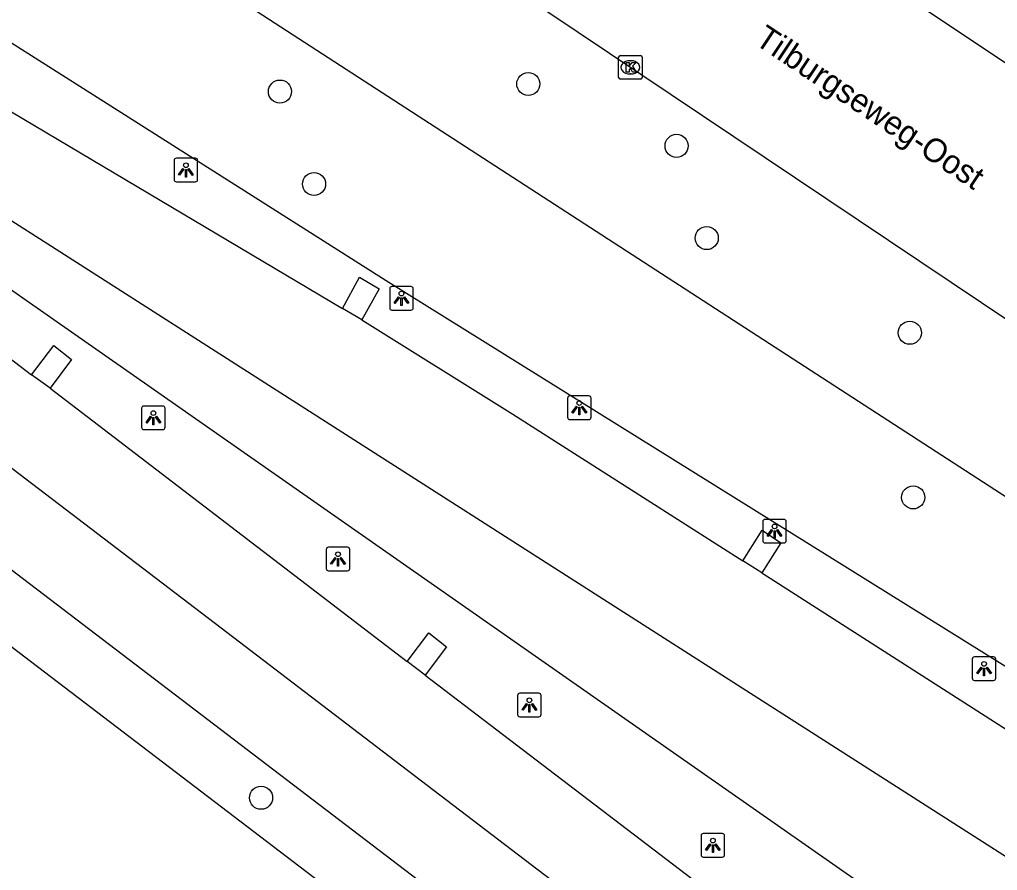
# Model space of a CAD drawing. Extents: x 158352 to 159489, y 383828 to 384597.
# Drawn here: x 158662.39 to 158703.83, y 383993.35 to 384029.38 of the extents above; entities that cross this region are included whole.
import ezdxf

# ---------------------------------------------------------------- set-up
doc = ezdxf.new("R2010")
doc.units = 0
for name, color, linetype in [('IMGEO_Berm_groen', 7, 'Continuous'), ('IMGEO_Boom', 7, 'Continuous'), ('IMGEO_Groenvoorziening', 7, 'Continuous'), ('IMGEO_Kolk', 7, 'Continuous'), ('IMGEO_Lichtpunt', 7, 'Continuous'), ('IMGEO_Openbare_ruimte_label', 7, 'Continuous'), ('IMGEO_Rijbaan_lokaal_open', 7, 'Continuous'), ('IMGEO_Rijbaan_regionaal_gesloten', 7, 'Continuous')]:
    doc.layers.add(name, color=color, linetype=linetype)

msp = doc.modelspace()

# ---------------------------------------------------------------- linework, layer by layer
at = {"layer": 'IMGEO_Berm_groen'}
for points in [[(158809.728, 383931.93), (158795.981, 383941.779), (158765.871, 383961.56), (158707.358, 384000), (158677.929, 384018.316), (158661.741, 384028.584), (158651.483, 384034.675), (158626.962, 384050.112), (158614.378, 384057.858), (158613.62, 384057.184)], [(158658.997, 384020.06), (158719.87, 383977.549)]]:
    msp.add_lwpolyline(points, dxfattribs=at)
at = {"layer": 'IMGEO_Boom'}
for centre in [(158683.946, 384026.656), (158673.421, 384026.335), (158690.228, 384024.035), (158674.866, 384022.42), (158691.508, 384020.131), (158700.113, 384016.119), (158700.256, 384009.149), (158672.622, 383996.426)]:
    msp.add_circle(centre, 0.489, dxfattribs=at)
at = {"layer": 'IMGEO_Groenvoorziening'}
msp.add_lwpolyline([(158631.002, 384057.298), (158666.397, 384033.665), (158718.365, 384000), (158753.016, 383977.553), (158769.011, 383966.352)], dxfattribs=at)
at = {"layer": 'IMGEO_Kolk'}
for p, q in [((158687.848, 384027.86), (158688.7, 384027.86)), ((158687.773, 384026.934), (158687.773, 384027.786)), ((158688.261, 384027.64), (158688.286, 384027.64)), ((158688.774, 384027.786), (158688.774, 384026.934)), ((158688.284, 384027.08), (158688.259, 384027.08)), ((158688.7, 384026.86), (158687.848, 384026.86))]:
    msp.add_line(p, q, dxfattribs=at)
for points in [[(158687.848, 384027.86), (158688.7, 384027.86)], [(158687.773, 384026.934), (158687.773, 384027.786)], [(158688.094, 384027.56), (158688.217, 384027.56), (158688.217, 384027.409), (158688.347, 384027.56), (158688.511, 384027.56), (158688.365, 384027.409), (158688.518, 384027.16), (158688.366, 384027.16), (158688.281, 384027.324), (158688.217, 384027.257), (158688.217, 384027.16), (158688.094, 384027.16), (158688.094, 384027.56)], [(158688.774, 384027.786), (158688.774, 384026.934)], [(158688.7, 384026.86), (158687.848, 384026.86)]]:
    msp.add_lwpolyline(points, dxfattribs=at)
for centre, start, end in [((158687.85, 384027.784), 91.552, 178.448), ((158687.85, 384027.784), 91.552, 178.448), ((158688.698, 384027.784), 1.552, 88.448), ((158688.698, 384027.784), 1.552, 88.448), ((158687.85, 384026.936), 181.552, 268.448), ((158687.85, 384026.936), 181.552, 268.448), ((158688.698, 384026.936), 271.552, 358.448), ((158688.698, 384026.936), 271.552, 358.448)]:
    msp.add_arc(centre, 0.0765, start, end, dxfattribs=at)
for centre, major_axis, ratio, start_param, end_param in [((158688.26, 384027.36), (-0.387, 0.002), 0.722429, 4.712389, 7.853982), ((158688.285, 384027.36), (-0.39, 0.002), 0.717154, 1.570796, 4.712389)]:
    msp.add_ellipse(centre, major_axis=major_axis, ratio=ratio, start_param=start_param, end_param=end_param, dxfattribs=at)
at = {"layer": 'IMGEO_Lichtpunt'}
for p, q in [((158668.938, 384023.414), (158668.938, 384022.607)), ((158668.938, 384023.414), (158668.938, 384022.607)), ((158669.84, 384023.509), (158669.032, 384023.509)), ((158669.84, 384023.509), (158669.032, 384023.509)), ((158669.934, 384022.607), (158669.934, 384023.414)), ((158669.934, 384022.607), (158669.934, 384023.414)), ((158669.032, 384022.513), (158669.84, 384022.513)), ((158669.032, 384022.513), (158669.84, 384022.513)), ((158678.072, 384017.983), (158678.072, 384017.176)), ((158678.072, 384017.983), (158678.072, 384017.176)), ((158678.974, 384018.078), (158678.166, 384018.078)), ((158678.974, 384018.078), (158678.166, 384018.078)), ((158679.068, 384017.176), (158679.068, 384017.983)), ((158679.068, 384017.176), (158679.068, 384017.983)), ((158678.166, 384017.082), (158678.974, 384017.082)), ((158678.166, 384017.082), (158678.974, 384017.082)), ((158685.609, 384013.347), (158685.609, 384012.54)), ((158685.609, 384013.347), (158685.609, 384012.54)), ((158686.511, 384013.442), (158685.703, 384013.442)), ((158686.511, 384013.442), (158685.703, 384013.442)), ((158686.605, 384012.54), (158686.605, 384013.347)), ((158686.605, 384012.54), (158686.605, 384013.347)), ((158667.56, 384012.922), (158667.56, 384012.115)), ((158667.56, 384012.922), (158667.56, 384012.115)), ((158668.462, 384013.017), (158667.654, 384013.017)), ((158668.462, 384013.017), (158667.654, 384013.017)), ((158668.556, 384012.115), (158668.556, 384012.922)), ((158668.556, 384012.115), (158668.556, 384012.922)), ((158685.703, 384012.446), (158686.511, 384012.446)), ((158685.703, 384012.446), (158686.511, 384012.446)), ((158667.654, 384012.021), (158668.462, 384012.021)), ((158667.654, 384012.021), (158668.462, 384012.021)), ((158693.882, 384008.121), (158693.882, 384007.314)), ((158693.882, 384008.121), (158693.882, 384007.314)), ((158694.784, 384008.216), (158693.976, 384008.216)), ((158694.784, 384008.216), (158693.976, 384008.216)), ((158694.878, 384007.314), (158694.878, 384008.121)), ((158694.878, 384007.314), (158694.878, 384008.121)), ((158693.976, 384007.22), (158694.784, 384007.22)), ((158693.976, 384007.22), (158694.784, 384007.22)), ((158675.383, 384006.939), (158675.383, 384006.132)), ((158675.383, 384006.939), (158675.383, 384006.132)), ((158676.285, 384007.034), (158675.477, 384007.034)), ((158676.285, 384007.034), (158675.477, 384007.034)), ((158676.379, 384006.132), (158676.379, 384006.939)), ((158676.379, 384006.132), (158676.379, 384006.939)), ((158675.477, 384006.038), (158676.285, 384006.038)), ((158675.477, 384006.038), (158676.285, 384006.038)), ((158702.76, 384002.297), (158702.76, 384001.49)), ((158702.76, 384002.297), (158702.76, 384001.49)), ((158703.662, 384002.392), (158702.854, 384002.392)), ((158703.662, 384002.392), (158702.854, 384002.392)), ((158703.756, 384001.49), (158703.756, 384002.297)), ((158703.756, 384001.49), (158703.756, 384002.297)), ((158702.854, 384001.396), (158703.662, 384001.396)), ((158702.854, 384001.396), (158703.662, 384001.396)), ((158683.493, 384000.755), (158683.493, 383999.948)), ((158683.493, 384000.755), (158683.493, 383999.948)), ((158684.395, 384000.85), (158683.587, 384000.85)), ((158684.395, 384000.85), (158683.587, 384000.85)), ((158684.489, 383999.948), (158684.489, 384000.755)), ((158684.489, 383999.948), (158684.489, 384000.755)), ((158683.587, 383999.854), (158684.395, 383999.854)), ((158683.587, 383999.854), (158684.395, 383999.854)), ((158691.269, 383994.813), (158691.269, 383994.006)), ((158691.269, 383994.813), (158691.269, 383994.006)), ((158692.171, 383994.908), (158691.363, 383994.908)), ((158692.171, 383994.908), (158691.363, 383994.908)), ((158692.265, 383994.006), (158692.265, 383994.813)), ((158692.265, 383994.006), (158692.265, 383994.813)), ((158691.363, 383993.912), (158692.171, 383993.912)), ((158691.363, 383993.912), (158692.171, 383993.912))]:
    msp.add_line(p, q, dxfattribs=at)
for points in [[(158669.312, 384023.078), (158669.351, 384023.05), (158669.163, 384022.788), (158669.125, 384022.815), (158669.312, 384023.078)], [(158669.414, 384023.03), (158669.461, 384023.03), (158669.461, 384022.708), (158669.414, 384022.708), (158669.414, 384023.03)], [(158669.524, 384023.05), (158669.562, 384023.077), (158669.749, 384022.815), (158669.71, 384022.787), (158669.524, 384023.05)], [(158678.446, 384017.647), (158678.485, 384017.619), (158678.297, 384017.357), (158678.259, 384017.384), (158678.446, 384017.647)], [(158678.548, 384017.599), (158678.595, 384017.599), (158678.595, 384017.277), (158678.548, 384017.277), (158678.548, 384017.599)], [(158678.658, 384017.619), (158678.696, 384017.646), (158678.883, 384017.384), (158678.844, 384017.356), (158678.658, 384017.619)], [(158685.983, 384013.011), (158686.022, 384012.983), (158685.834, 384012.721), (158685.796, 384012.748), (158685.983, 384013.011)], [(158686.085, 384012.963), (158686.132, 384012.963), (158686.132, 384012.641), (158686.085, 384012.641), (158686.085, 384012.963)], [(158686.195, 384012.983), (158686.233, 384013.01), (158686.42, 384012.748), (158686.381, 384012.72), (158686.195, 384012.983)], [(158667.934, 384012.586), (158667.973, 384012.558), (158667.785, 384012.296), (158667.747, 384012.323), (158667.934, 384012.586)], [(158668.036, 384012.538), (158668.083, 384012.538), (158668.083, 384012.216), (158668.036, 384012.216), (158668.036, 384012.538)], [(158668.146, 384012.558), (158668.184, 384012.585), (158668.371, 384012.323), (158668.332, 384012.295), (158668.146, 384012.558)], [(158694.256, 384007.785), (158694.295, 384007.757), (158694.107, 384007.495), (158694.069, 384007.522), (158694.256, 384007.785)], [(158694.358, 384007.737), (158694.405, 384007.737), (158694.405, 384007.415), (158694.358, 384007.415), (158694.358, 384007.737)], [(158694.468, 384007.757), (158694.506, 384007.784), (158694.693, 384007.522), (158694.654, 384007.494), (158694.468, 384007.757)], [(158675.757, 384006.603), (158675.796, 384006.575), (158675.608, 384006.313), (158675.57, 384006.34), (158675.757, 384006.603)], [(158675.859, 384006.555), (158675.906, 384006.555), (158675.906, 384006.233), (158675.859, 384006.233), (158675.859, 384006.555)], [(158675.969, 384006.575), (158676.007, 384006.602), (158676.194, 384006.34), (158676.155, 384006.312), (158675.969, 384006.575)], [(158703.134, 384001.961), (158703.173, 384001.933), (158702.985, 384001.671), (158702.947, 384001.698), (158703.134, 384001.961)], [(158703.236, 384001.913), (158703.283, 384001.913), (158703.283, 384001.591), (158703.236, 384001.591), (158703.236, 384001.913)], [(158703.346, 384001.933), (158703.384, 384001.96), (158703.571, 384001.698), (158703.532, 384001.67), (158703.346, 384001.933)], [(158683.867, 384000.419), (158683.906, 384000.391), (158683.718, 384000.129), (158683.68, 384000.156), (158683.867, 384000.419)], [(158683.969, 384000.371), (158684.016, 384000.371), (158684.016, 384000.049), (158683.969, 384000.049), (158683.969, 384000.371)], [(158684.079, 384000.391), (158684.117, 384000.418), (158684.304, 384000.156), (158684.265, 384000.128), (158684.079, 384000.391)], [(158691.643, 383994.477), (158691.682, 383994.449), (158691.494, 383994.187), (158691.456, 383994.214), (158691.643, 383994.477)], [(158691.745, 383994.429), (158691.792, 383994.429), (158691.792, 383994.107), (158691.745, 383994.107), (158691.745, 383994.429)], [(158691.855, 383994.449), (158691.893, 383994.476), (158692.08, 383994.214), (158692.041, 383994.186), (158691.855, 383994.449)]]:
    msp.add_lwpolyline(points, dxfattribs=at)
for centre in [(158669.437, 384023.212), (158678.571, 384017.781), (158686.108, 384013.145), (158668.059, 384012.72), (158694.381, 384007.919), (158675.882, 384006.737), (158703.259, 384002.095), (158683.992, 384000.553), (158691.768, 383994.611)]:
    msp.add_circle(centre, 0.0994, dxfattribs=at)
for centre, start, end in [((158669.032, 384023.414), 90, 180), ((158669.032, 384023.414), 90, 180), ((158669.84, 384023.414), 0, 90), ((158669.84, 384023.414), 0, 90), ((158669.032, 384022.607), 180, 270), ((158669.032, 384022.607), 180, 270), ((158669.84, 384022.607), 270, 0), ((158669.84, 384022.607), 270, 360), ((158678.166, 384017.983), 90, 180), ((158678.166, 384017.983), 90, 180), ((158678.974, 384017.983), 0, 90), ((158678.974, 384017.983), 0, 90), ((158678.166, 384017.176), 180, 270), ((158678.166, 384017.176), 180, 270), ((158678.974, 384017.176), 270, 0), ((158678.974, 384017.176), 270, 360), ((158685.703, 384013.347), 90, 180), ((158685.703, 384013.347), 90, 180), ((158686.511, 384013.347), 0, 90), ((158686.511, 384013.347), 0, 90), ((158667.654, 384012.922), 90, 180), ((158667.654, 384012.922), 90, 180), ((158668.462, 384012.922), 0, 90), ((158668.462, 384012.922), 0, 90), ((158685.703, 384012.54), 180, 270), ((158685.703, 384012.54), 180, 270), ((158686.511, 384012.54), 270, 0), ((158686.511, 384012.54), 270, 360), ((158667.654, 384012.115), 180, 270), ((158667.654, 384012.115), 180, 270), ((158668.462, 384012.115), 270, 0), ((158668.462, 384012.115), 270, 360), ((158693.976, 384008.121), 90, 180), ((158693.976, 384008.121), 90, 180), ((158694.784, 384008.121), 0, 90), ((158694.784, 384008.121), 0, 90), ((158693.976, 384007.314), 180, 270), ((158693.976, 384007.314), 180, 270), ((158694.784, 384007.314), 270, 0), ((158694.784, 384007.314), 270, 360), ((158675.477, 384006.939), 90, 180), ((158675.477, 384006.939), 90, 180), ((158676.285, 384006.939), 0, 90), ((158676.285, 384006.939), 0, 90), ((158675.477, 384006.132), 180, 270), ((158675.477, 384006.132), 180, 270), ((158676.285, 384006.132), 270, 0), ((158676.285, 384006.132), 270, 360), ((158702.854, 384002.297), 90, 180), ((158702.854, 384002.297), 90, 180), ((158703.662, 384002.297), 0, 90), ((158703.662, 384002.297), 0, 90), ((158702.854, 384001.49), 180, 270), ((158702.854, 384001.49), 180, 270), ((158703.662, 384001.49), 270, 0), ((158703.662, 384001.49), 270, 360), ((158683.587, 384000.755), 90, 180), ((158683.587, 384000.755), 90, 180), ((158684.395, 384000.755), 0, 90), ((158684.395, 384000.755), 0, 90), ((158683.587, 383999.948), 180, 270), ((158683.587, 383999.948), 180, 270), ((158684.395, 383999.948), 270, 0), ((158684.395, 383999.948), 270, 360), ((158691.363, 383994.813), 90, 180), ((158691.363, 383994.813), 90, 180), ((158692.171, 383994.813), 0, 90), ((158692.171, 383994.813), 0, 90), ((158691.363, 383994.006), 180, 270), ((158691.363, 383994.006), 180, 270), ((158692.171, 383994.006), 270, 0), ((158692.171, 383994.006), 270, 360)]:
    msp.add_arc(centre, 0.0946, start, end, dxfattribs=at)
at = {"layer": 'IMGEO_Rijbaan_lokaal_open'}
for points in [[(158688.754, 384037.85), (158713.384, 384021.411)], [(158708.423, 384013.859), (158683.45, 384030.599), (158676.121, 384035.659)], [(158676.071, 384017.151), (158676.794, 384018.469), (158677.624, 384017.986), (158676.885, 384016.664)], [(158662.899, 384014.332), (158663.837, 384015.576), (158664.593, 384014.985), (158663.682, 384013.776)], [(158693.043, 384006.463), (158693.853, 384007.754), (158694.653, 384007.224), (158693.84, 384005.947)], [(158678.81, 384002.198), (158679.727, 384003.414), (158680.483, 384002.822), (158679.572, 384001.613)]]:
    msp.add_lwpolyline(points, dxfattribs=at)
at = {"layer": 'IMGEO_Rijbaan_regionaal_gesloten'}
for points in [[(158876.311, 383847.075), (158853.2, 383864.631), (158826.26, 383885.172), (158810.298, 383897.342), (158786.867, 383915.207), (158739.488, 383951.331), (158697.831, 383983.092), (158678.288, 383997.993), (158670.924, 384003.608), (158635.896, 384030.315), (158604.629, 384054.077)], [(158872.742, 383845.398), (158840.416, 383870.111), (158712.448, 383967.648), (158601.783, 384051.997)], [(158870.149, 383844.179), (158710.894, 383965.575), (158599.607, 384050.406)], [(158659.633, 384026.899), (158676.071, 384017.151)], [(158809.311, 383924.969), (158764.39, 383955.088), (158755.227, 383961.2), (158745.974, 383967.224), (158723.089, 383981.844), (158660.628, 384021.748)], [(158658.2, 384017.903), (158662.899, 384014.332)], [(158676.885, 384016.664), (158676.071, 384017.151)], [(158676.885, 384016.664), (158683.291, 384012.679), (158693.043, 384006.463)], [(158663.682, 384013.776), (158662.899, 384014.332)], [(158663.682, 384013.776), (158678.81, 384002.198)], [(158693.84, 384005.947), (158693.043, 384006.463)], [(158693.84, 384005.947), (158709.941, 383995.652)], [(158679.572, 384001.613), (158678.81, 384002.198)], [(158679.572, 384001.613), (158694.758, 383990.039)]]:
    msp.add_lwpolyline(points, dxfattribs=at)

# ---------------------------------------------------------------- texts
at = {"layer": 'IMGEO_Openbare_ruimte_label'}
msp.add_text('Tilburgseweg-Oost', height=1, rotation=326.294, dxfattribs=at).set_placement((158693.492, 384028.376))

doc.saveas('drawing.dxf')
